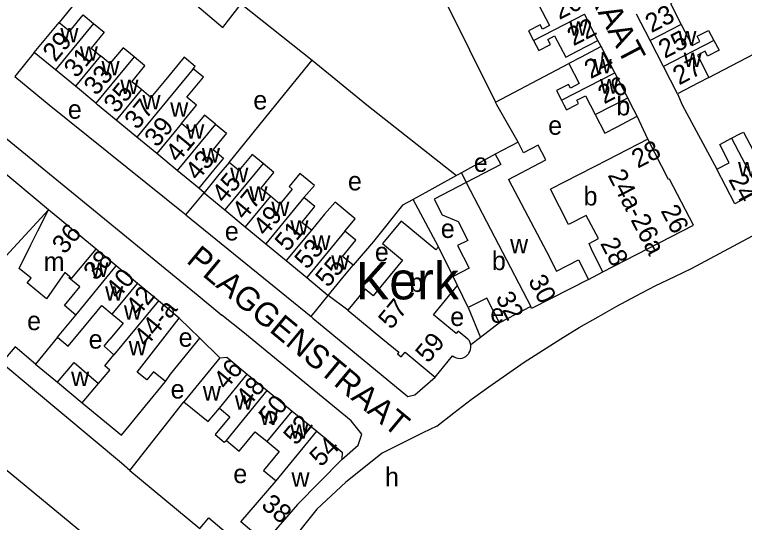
# Model space of a CAD drawing. Extents: x 158356 to 159894, y 383831 to 385260.
# Drawn here: x 159223.4 to 159379.2, y 384210.9 to 384319.2 of the extents above; entities that cross this region are included whole.
import ezdxf

# ---------------------------------------------------------------- set-up
doc = ezdxf.new("R2010")
doc.units = 0
for name, color, linetype in [('BLT_Basislijn', 7, 'Continuous'), ('BLT_Bebouwing', 7, 'Continuous'), ('BLT_Bebouwing_beschrifting', 7, 'Continuous'), ('BLT_Centroide', 7, 'Continuous'), ('BLT_Huisnummer', 7, 'Continuous'), ('BLT_Huisnummer_ tussenligend', 7, 'Continuous'), ('BLT_Huisnummer_reeks', 7, 'Continuous'), ('BLT_Onderverdeling_panden', 7, 'Continuous'), ('BLT_Straatnaam', 7, 'Continuous')]:
    doc.layers.add(name, color=color, linetype=linetype)

msp = doc.modelspace()

# ---------------------------------------------------------------- linework, layer by layer
at = {"layer": 'BLT_Basislijn'}
for p, q in [((159303.08, 384346.8), (159326.09, 384300.52)), ((159246.67, 384334.38), (159232.88, 384317.57)), ((159271.73, 384321.55), (159286.92, 384309.47)), ((159348.63, 384312.39), (159347.94, 384313.73)), ((159371.64, 384305.8), (159385.33, 384312.96)), ((159227.6, 384311.17), (159223.42, 384306.02)), ((159326.09, 384300.52), (159341.72, 384308.8)), ((159358.6, 384292.65), (159356.34, 384297.54)), ((159367.92, 384265.07), (159423.05, 384294.6)), ((159326.02, 384289.46), (159318.79, 384285.47)), ((159230.61, 384277.56), (159216.55, 384289.3)), ((159317.76, 384284.9), (159308.48, 384279.78)), ((159318.79, 384285.47), (159317.76, 384284.9)), ((159318.79, 384285.47), (159319.83, 384283.42)), ((159263.85, 384281.22), (159262.7, 384282.18)), ((159259.93, 384276.53), (159263.85, 384281.22)), ((159313.87, 384269.66), (159308.48, 384279.78)), ((159221.53, 384267.67), (159230.61, 384277.56)), ((159259.93, 384276.53), (159286.69, 384254.81)), ((159345.91, 384262.74), (159349.01, 384264.35)), ((159262.59, 384259.31), (159267.64, 384255.09)), ((159286.69, 384254.81), (159290.37, 384259.32)), ((159294.56, 384256.13), (159290.37, 384259.32)), ((159320.26, 384256.7), (159322.84, 384250.36)), ((159262.93, 384250.18), (159258.56, 384254.48)), ((159272.1, 384251.54), (159267.64, 384255.09)), ((159326.9, 384253.48), (159322.84, 384250.36)), ((159232.54, 384250.38), (159227.82, 384244.65)), ((159267.21, 384245.97), (159262.93, 384250.18)), ((159322.84, 384250.36), (159320.81, 384248.8)), ((159227.82, 384244.65), (159232.53, 384240.77)), ((159247.96, 384221.99), (159259.55, 384236.62)), ((159208.18, 384233.17), (159244.02, 384203.65)), ((159247.96, 384221.99), (159262.91, 384209.55)), ((159262.91, 384209.55), (159264.83, 384211.86)), ((159264.83, 384211.86), (159274.83, 384203.55))]:
    msp.add_line(p, q, dxfattribs=at)
for points in [[(159252.62, 384329.44), (159267.86, 384316.46), (159271.73, 384321.55)], [(159269.17, 384287.66), (159279.17, 384300), (159286.92, 384309.47)], [(159286.92, 384309.47), (159298.59, 384300), (159317.76, 384284.9)], [(159223.42, 384306.02), (159230.8, 384300), (159259.72, 384276.7), (159259.93, 384276.53)], [(159364.95, 384302.35), (159365.93, 384300), (159373.34, 384286.22)], [(159330.91, 384291.98), (159326.35, 384300), (159326.09, 384300.52)], [(159210.97, 384293.91), (159214.28, 384296.93), (159215.48, 384297.74), (159262.59, 384259.31)], [(159308.48, 384279.78), (159306.23, 384278.53), (159299.99, 384270.84), (159295.68, 384265.74)], [(159313.55, 384231.42), (159317.19, 384234.28), (159320.88, 384237.07), (159324.61, 384239.8), (159328.39, 384242.46), (159332.22, 384245.06), (159336.09, 384247.59), (159340.01, 384250.05), (159343.96, 384252.45), (159347.96, 384254.77), (159352, 384257.03), (159356.07, 384259.22), (159360.18, 384261.33), (159364.33, 384263.38), (159367.92, 384265.07)], [(159286.69, 384254.81), (159287.1, 384254.48), (159307.36, 384237.73), (159308.88, 384238.09), (159313.19, 384241.9)], [(159293.27, 384224.32), (159296.73, 384227.34), (159297.54, 384229.72), (159295.25, 384232.52), (159272.1, 384251.54)], [(159255.62, 384240.93), (159256.67, 384242.48), (159262.93, 384250.18)], [(159227.82, 384244.65), (159223.54, 384248.33), (159220.59, 384244.95)], [(159247.96, 384221.99), (159246.23, 384223.49), (159227.24, 384239.36), (159220.59, 384244.95)], [(159313.55, 384231.42), (159310.54, 384229.96), (159301.86, 384225.62), (159294.09, 384219.45), (159287.92, 384213.73), (159281.76, 384205.96)]]:
    msp.add_lwpolyline(points, dxfattribs=at)
at = {"layer": 'BLT_Bebouwing'}
for p, q in [((159347.94, 384313.73), (159345.05, 384319.3)), ((159359.09, 384313.69), (159356.19, 384319.29)), ((159227.6, 384311.17), (159232.88, 384317.57)), ((159361.94, 384308.17), (159359.09, 384313.69)), ((159351.52, 384306.82), (159348.63, 384312.39)), ((159232.11, 384307.45), (159227.6, 384311.17)), ((159364.95, 384302.35), (159361.94, 384308.17)), ((159236.37, 384303.93), (159232.11, 384307.45)), ((159354.3, 384301.47), (159351.52, 384306.82)), ((159240.72, 384300.33), (159236.37, 384303.93)), ((159249.51, 384293.07), (159245.09, 384296.73)), ((159253.73, 384289.59), (159249.51, 384293.07)), ((159330.91, 384291.98), (159326.02, 384289.46)), ((159258.13, 384285.96), (159253.73, 384289.59)), ((159262.7, 384282.18), (159258.13, 384285.96)), ((159263.85, 384281.22), (159268.27, 384277.57)), ((159240.8, 384269.15), (159230.61, 384277.56)), ((159268.27, 384277.57), (159272.63, 384273.97)), ((159289.57, 384276.63), (159286.75, 384273.21)), ((159272.63, 384273.97), (159277.01, 384270.35)), ((159277.01, 384270.35), (159281.39, 384266.73)), ((159317.03, 384263.34), (159313.87, 384269.66)), ((159245.1, 384265.6), (159240.8, 384269.15)), ((159281.39, 384266.73), (159285.75, 384263.13)), ((159249.62, 384261.86), (159245.1, 384265.6)), ((159285.75, 384263.13), (159290.37, 384259.32)), ((159254.09, 384258.17), (159249.62, 384261.86)), ((159320.26, 384256.7), (159317.98, 384261.45)), ((159258.56, 384254.48), (159254.09, 384258.17)), ((159333.58, 384256.92), (159326.9, 384253.48)), ((159294.56, 384256.13), (159301.99, 384250)), ((159232.54, 384250.38), (159236.46, 384255.13)), ((159313.19, 384241.9), (159316.92, 384246.43)), ((159273.08, 384242.52), (159277.34, 384239.01)), ((159232.53, 384240.77), (159237.82, 384236.41)), ((159277.34, 384239.01), (159282.68, 384234.62)), ((159259.55, 384236.62), (159264.75, 384232.39)), ((159264.75, 384232.39), (159267.12, 384235.27)), ((159282.68, 384234.62), (159287.9, 384230.33))]:
    msp.add_line(p, q, dxfattribs=at)
for points in [[(159366.85, 384324.8), (159367.96, 384322.65), (159365.54, 384321.4), (159365.02, 384322.41), (159363.42, 384321.59), (159365.73, 384317.13)], [(159335.28, 384321.37), (159337.61, 384316.88), (159336.11, 384316.09), (159335.6, 384317.07), (159333.09, 384315.77), (159334.19, 384313.66)], [(159232.88, 384317.57), (159235.15, 384315.7), (159238.03, 384319.19), (159240.27, 384317.34)], [(159240.27, 384317.34), (159242.51, 384315.48), (159239.71, 384312.09), (159241.73, 384310.42)], [(159365.73, 384317.13), (159368.04, 384312.66), (159369.67, 384313.51), (159369.12, 384314.59), (159371.58, 384315.86), (159372.69, 384313.73)], [(159334.19, 384313.66), (159335.29, 384311.54), (159337.79, 384312.84), (159337.22, 384313.93), (159338.68, 384314.69), (159341.05, 384310.14), (159343.5, 384311.42), (159347.94, 384313.73)], [(159372.69, 384313.73), (159373.79, 384311.6), (159371.36, 384310.34), (159370.81, 384311.39), (159369.18, 384310.55), (159371.64, 384305.8)], [(159248.89, 384310.22), (159246.55, 384312.15), (159243.75, 384308.76), (159241.73, 384310.42)], [(159348.63, 384312.39), (159344.2, 384310.08), (159341.72, 384308.8)], [(159250.47, 384303.24), (159248.44, 384304.91), (159251.22, 384308.29), (159248.89, 384310.22)], [(159261.53, 384307.68), (159261.93, 384308.16), (159259.56, 384310.11), (159255.29, 384304.94), (159252.5, 384301.56), (159250.47, 384303.24)], [(159341.72, 384308.8), (159343.94, 384304.53), (159342.07, 384303.56), (159341.67, 384304.32), (159339.11, 384303), (159340.18, 384300.93)], [(159259.03, 384296.01), (159262.23, 384299.88), (159260.17, 384301.58), (159263.72, 384305.88), (159261.53, 384307.68)], [(159371.64, 384305.8), (159369.4, 384304.64), (159364.95, 384302.35)], [(159340.18, 384300.93), (159340.67, 384300), (159341.23, 384298.92), (159343.32, 384300), (159343.77, 384300.24), (159343.41, 384300.94), (159345.3, 384301.92), (159346.29, 384300), (159347.36, 384297.94)], [(159356.34, 384297.54), (159355.06, 384300), (159354.3, 384301.47)], [(159245.09, 384296.73), (159241.12, 384300), (159240.72, 384300.33)], [(159266.29, 384295.85), (159263.95, 384297.78), (159261.05, 384294.28), (159259.03, 384296.01)], [(159347.36, 384297.94), (159349.43, 384293.96), (159351.9, 384295.24), (159356.34, 384297.54)], [(159266.29, 384295.85), (159268.64, 384293.91), (159265.77, 384290.44), (159268, 384288.6), (159265.89, 384286.04), (159262.7, 384282.18)], [(159376.47, 384292.83), (159378.37, 384293.82), (159379.01, 384294.16), (159380.99, 384290.4), (159383.32, 384291.62)], [(159358.6, 384292.65), (159354.15, 384290.36), (159350.03, 384288.24), (159337.84, 384282)], [(159349.01, 384264.35), (159368.32, 384274.29), (159363.24, 384284.13), (159363.04, 384284.03), (159358.6, 384292.65)], [(159373.34, 384286.22), (159375.98, 384287.61), (159373.94, 384291.5), (159376.47, 384292.83)], [(159328.84, 384284.07), (159336.78, 384288.27), (159335.2, 384291.33), (159332.08, 384289.72), (159330.91, 384291.98)], [(159326.02, 384289.46), (159327.19, 384287.21), (159319.83, 384283.42)], [(159276.43, 384287.45), (159274.09, 384289.39), (159271.25, 384285.94), (159269.17, 384287.66)], [(159269.17, 384287.66), (159267.03, 384285.08), (159263.85, 384281.22)], [(159278, 384280.47), (159275.98, 384282.14), (159278.77, 384285.52), (159276.43, 384287.45)], [(159285.16, 384280.22), (159287.42, 384282.75), (159284.3, 384285.33), (159281.98, 384282.53), (159282.68, 384282.01), (159280.03, 384278.79), (159278, 384280.47)], [(159382.36, 384281.59), (159377.19, 384278.88), (159373.34, 384286.22)], [(159319.83, 384283.42), (159312.94, 384279.87), (159314.68, 384276.49), (159318.08, 384275.08), (159320.16, 384271.06), (159317.98, 384269.94), (159320.47, 384265.12), (159317.03, 384263.34)], [(159328.84, 384284.07), (159335.66, 384271.13), (159336.94, 384268.65), (159339.1, 384264.46), (159343.78, 384266.88), (159345.91, 384262.74)], [(159349.01, 384264.35), (159346.72, 384268.79), (159346.05, 384270.4), (159348.03, 384271.47), (159345.46, 384276.38), (159341.65, 384274.42), (159337.84, 384282)], [(159286.75, 384273.21), (159284.72, 384274.9), (159287.51, 384278.28), (159285.16, 384280.22)], [(159293.93, 384273.03), (159296.1, 384275.64), (159291.85, 384279.17), (159289.57, 384276.63)], [(159224.36, 384265.08), (159226.87, 384270.1), (159228.37, 384273.09), (159230.61, 384277.56)], [(159313.87, 384269.66), (159313.35, 384269.03), (159305.9, 384275.18), (159301.93, 384270.39), (159306.23, 384266.84), (159299.94, 384259.23), (159298.27, 384260.61), (159294.56, 384256.13)], [(159295.68, 384265.74), (159293.38, 384267.64), (159296.25, 384271.11), (159293.93, 384273.03)], [(159235.2, 384263.3), (159234.15, 384264.17), (159230.22, 384258.61), (159226.1, 384262.01), (159226.9, 384262.98), (159224.36, 384265.08)], [(159290.37, 384259.32), (159293.55, 384263.17), (159295.68, 384265.74)], [(159236.46, 384255.13), (159234.01, 384257.15), (159237.29, 384261.12), (159234.98, 384263.03), (159235.2, 384263.3)], [(159320.19, 384250), (159318.11, 384251.68), (159317.67, 384251.16), (159312.8, 384255.18), (159317.98, 384261.45)], [(159345.91, 384262.74), (159333.79, 384256.5), (159333.58, 384256.92)], [(159326.9, 384253.48), (159324.2, 384258.72), (159320.26, 384256.7)], [(159232.54, 384250.38), (159234.85, 384248.48), (159238.69, 384253.12), (159242.03, 384257.16), (159244.24, 384255.34)], [(159244.24, 384255.34), (159246.57, 384253.41), (159244.51, 384250.91), (159243.73, 384249.97)], [(159255.62, 384240.93), (159253.06, 384243.04), (159251.61, 384241.28), (159249.59, 384242.94), (159258.56, 384254.48)], [(159244.58, 384246.6), (159242.49, 384248.45), (159243.73, 384249.97)], [(159301.99, 384250), (159305.42, 384247.18), (159305.14, 384246.84), (159305.93, 384246.18), (159306.76, 384247.19), (159313.19, 384241.9)], [(159320.81, 384248.8), (159320.69, 384249.22), (159320.5, 384249.6), (159320.24, 384249.94), (159320.19, 384250)], [(159320.37, 384247), (159320.6, 384247.36), (159320.76, 384247.76), (159320.83, 384248.18), (159320.83, 384248.61), (159320.81, 384248.8)], [(159241.33, 384240.55), (159243.73, 384243.39), (159242.65, 384244.31), (159244.58, 384246.6)], [(159267.21, 384245.97), (159264.04, 384242.11), (159259.55, 384236.62), (159259.55, 384236.62)], [(159267.21, 384245.97), (159268.71, 384246.11), (159273.08, 384242.52)], [(159316.92, 384246.43), (159317.27, 384246.19), (159317.66, 384246.01), (159318.07, 384245.91), (159318.5, 384245.88), (159318.92, 384245.94), (159319.33, 384246.07), (159319.7, 384246.28), (159320.03, 384246.55), (159320.3, 384246.88), (159320.37, 384247)], [(159232.53, 384240.77), (159236.1, 384244.99), (159241.33, 384240.55)], [(159237.82, 384236.41), (159246.22, 384229.49), (159248.19, 384231.89), (159251.37, 384235.75), (159255.62, 384240.93)], [(159267.12, 384235.27), (159269.38, 384233.4), (159266.21, 384229.67), (159268.17, 384227.99), (159268.6, 384228.38)], [(159287.9, 384230.33), (159293.34, 384225.86), (159293.27, 384224.32)], [(159268.6, 384228.38), (159271.37, 384226.1), (159274.76, 384230.23), (159277.33, 384228.12)], [(159277.33, 384228.12), (159279.9, 384226.01), (159276.56, 384221.94), (159279.22, 384219.76)], [(159293.27, 384224.32), (159283.78, 384214.68), (159276.83, 384206.67)], [(159276.83, 384206.67), (159271.67, 384211), (159279.22, 384219.76)]]:
    msp.add_lwpolyline(points, dxfattribs=at)
at = {"layer": 'BLT_Onderverdeling_panden'}
for p, q in [((159334.19, 384313.66), (159345.05, 384319.3)), ((159240.27, 384317.34), (159232.11, 384307.45)), ((159365.73, 384317.13), (159359.09, 384313.69)), ((159372.69, 384313.73), (159361.94, 384308.17)), ((159241.73, 384310.42), (159236.37, 384303.93)), ((159248.89, 384310.22), (159240.72, 384300.33)), ((159261.53, 384307.68), (159249.51, 384293.07)), ((159340.18, 384300.93), (159351.52, 384306.82)), ((159250.47, 384303.24), (159245.09, 384296.73)), ((159347.36, 384297.94), (159354.3, 384301.47)), ((159259.03, 384296.01), (159253.73, 384289.59)), ((159266.29, 384295.85), (159258.13, 384285.96)), ((159376.47, 384292.83), (159382.36, 384281.59)), ((159276.43, 384287.45), (159268.27, 384277.57)), ((159319.83, 384283.42), (159333.58, 384256.92)), ((159278, 384280.47), (159272.63, 384273.97)), ((159285.16, 384280.22), (159277.01, 384270.35)), ((159286.75, 384273.21), (159281.39, 384266.73)), ((159293.93, 384273.03), (159285.75, 384263.13)), ((159236.46, 384255.13), (159245.1, 384265.6)), ((159317.98, 384261.45), (159317.03, 384263.34)), ((159244.24, 384255.34), (159249.62, 384261.86)), ((159254.09, 384258.17), (159244.58, 384246.6)), ((159267.12, 384235.27), (159273.08, 384242.52)), ((159237.82, 384236.41), (159241.33, 384240.55)), ((159268.6, 384228.38), (159277.34, 384239.01)), ((159277.33, 384228.12), (159282.68, 384234.62)), ((159279.22, 384219.76), (159287.9, 384230.33))]:
    msp.add_line(p, q, dxfattribs=at)
msp.add_lwpolyline([(159235.2, 384263.3), (159235.58, 384262.96), (159240.8, 384269.15)], dxfattribs=at)

# ---------------------------------------------------------------- texts
at = {"layer": 'BLT_Bebouwing_beschrifting'}
msp.add_text('Kerk', height=8, rotation=359.9995, dxfattribs=at).set_placement((159296.25, 384258.47))
at = {"layer": 'BLT_Centroide'}
for s, p in [('w', (159341.83, 384314.72)), ('w', (159233.16, 384313.31)), ('w', (159365.11, 384312.66)), ('w', (159237.31, 384309.41)), ('w', (159347.02, 384306.66)), ('w', (159366.25, 384308.03)), ('w', (159241.94, 384306.25)), ('w', (159245.97, 384302.25)), ('w', (159348.4, 384302.38)), ('w', (159250.68, 384299)), ('e', (159274.36, 384298.98)), ('b', (159351.87, 384297.72)), ('w', (159256.61, 384297.41)), ('e', (159234.76, 384297.01)), ('w', (159260.02, 384292.72)), ('e', (159337.32, 384293.59)), ('w', (159263.38, 384287.66)), ('e', (159321.43, 384285.67)), ('w', (159269.43, 384283.47)), ('w', (159377.84, 384284.72)), ('e', (159294.56, 384281.72)), ('w', (159273.52, 384279.48)), ('b', (159344.88, 384278.5)), ('w', (159278.2, 384276.25)), ('e', (159268.28, 384271.04)), ('w', (159282.27, 384272.25)), ('e', (159314.39, 384271.57)), ('w', (159286.96, 384269.03)), ('w', (159329.18, 384268.3)), ('e', (159300.31, 384266.6)), ('m', (159229.6, 384264.55)), ('w', (159291, 384264.8)), ('b', (159325.3, 384264.7)), ('w', (159239.56, 384263.27)), ('b', (159307.7, 384260.05)), ('w', (159242.71, 384258.2)), ('w', (159246.72, 384254.15)), ('e', (159316.41, 384252.79)), ('e', (159324.97, 384253.48)), ('e', (159226.06, 384251.91)), ('e', (159239.2, 384247.96)), ('e', (159258.42, 384248.36)), ('w', (159247.74, 384246.52)), ('w', (159235.45, 384239.95)), ('e', (159256.71, 384237.31)), ('w', (159263.58, 384236.89)), ('w', (159270.41, 384234.94)), ('w', (159275.77, 384231.66)), ('w', (159282.23, 384228.75)), ('h', (159302.48, 384218.61)), ('e', (159270.09, 384219.27)), ('w', (159282.5, 384218.48))]:
    msp.add_text(s, height=4, dxfattribs=at).set_placement(p)
at = {"layer": 'BLT_Huisnummer'}
for s, rotation, p in [('22', 27.3639, (159342.71, 384312.44)), ('29', 50.4453, (159232.09, 384308.93)), ('24', 27.3639, (159346.36, 384305.41)), ('27', 27.4431, (159365.27, 384304.1)), ('33', 50.4453, (159240.86, 384301.75)), ('37', 50.4453, (159249.56, 384294.49)), ('43', 50.4453, (159262.51, 384283.59)), ('45', 50.4453, (159268.19, 384278.77)), ('24', 297.6509, (159375.72, 384284.05)), ('49', 50.4453, (159277, 384271.75)), ('36', 50.4489, (159234.09, 384267.91)), ('55', 50.4453, (159290.32, 384260.82)), ('40', 50.4489, (159245.52, 384258.34)), ('30', 297.2484, (159332.96, 384262.49)), ('32', 297.5143, (159326.01, 384258.88)), ('46', 50.4489, (159268.56, 384238.99)), ('50', 50.4489, (159278.19, 384231.37))]:
    msp.add_text(s, height=4, rotation=rotation, dxfattribs=at).set_placement(p)
at = {"layer": 'BLT_Huisnummer_ tussenligend'}
for s, rotation, p in [('20', 27.3639, (159339.71, 384318.05)), ('23', 27.4431, (159359.37, 384315.25)), ('25', 27.4431, (159362.2, 384309.76)), ('31', 50.4453, (159236.62, 384305.51)), ('26', 27.3639, (159349.27, 384300.06)), ('35', 50.4453, (159245.11, 384297.97)), ('39', 50.4453, (159253.81, 384290.72)), ('41', 50.4453, (159258.32, 384287.48)), ('47', 50.4453, (159272.49, 384275.21)), ('51', 50.4453, (159281.66, 384268.45)), ('53', 50.4453, (159285.86, 384264.68)), ('38', 50.4489, (159240.8, 384262.26)), ('42', 50.4489, (159249.83, 384254.64)), ('48', 50.4489, (159273.34, 384235.29)), ('52', 50.4489, (159283.49, 384227.14))]:
    msp.add_text(s, height=4, rotation=rotation, dxfattribs=at).set_placement(p)
at = {"layer": 'BLT_Huisnummer_reeks'}
for s, rotation, p in [('28', 27.2621, (159356.45, 384286.34)), ('24a-26a', 297.2617, (159349.95, 384284.98)), ('26', 297.2617, (159361.26, 384277.41)), ('28', 297.2563, (159348.35, 384270.43)), ('57', 50.5417, (159303.77, 384251.86)), ('44-a', 50.4456, (159251.53, 384248.13)), ('59', 50.4455, (159311.68, 384244.69)), ('54', 45.4554, (159288.8, 384222.55)), ('38', 319.9648, (159275.83, 384214.23))]:
    msp.add_text(s, height=4, rotation=rotation, dxfattribs=at).set_placement(p)
at = {"layer": 'BLT_Straatnaam'}
for s, rotation, p in [('CANADASTRAAT', 297.6478, (159328.68, 384356.27)), ('PLAGGENSTRAAT', 320.2686, (159259.86, 384266.46))]:
    msp.add_text(s, height=5, rotation=rotation, dxfattribs=at).set_placement(p)

doc.saveas('drawing.dxf')
